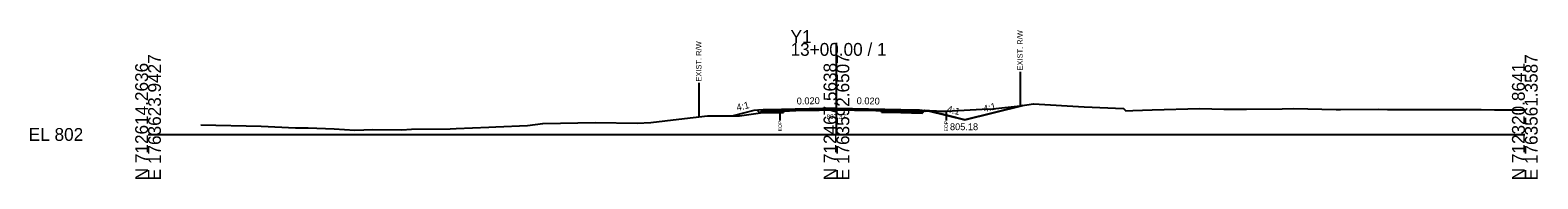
# Model space of a CAD drawing. Extents: x -26 to 1303, y -10 to 9524.
# Drawn here: x -25.7 to 302.8, y 2990.3 to 3022.8 of the extents above; entities that cross this region are included whole.
import ezdxf

# ---------------------------------------------------------------- set-up
doc = ezdxf.new("R2010")
doc.units = 0
for name, color, linetype in [('Default', 7, 'Continuous'), ('Exist CMT Pavement', 7, 'Continuous'), ('Exist Cross Section Cell', 7, 'Continuous'), ('Exist XS Center Line Elevation Label', 7, 'Continuous'), ('Exist XS Ground Line', 7, 'Continuous'), ('Old_Level_10', 7, 'Continuous'), ('Prop CMT Pvmt Course 1', 7, 'Continuous'), ('Prop CMT Pvmt Course 3', 7, 'Continuous'), ('Prop CMT Pvmt Surface', 7, 'Continuous'), ('Prop CMT Pvmt Surface Shoulder', 7, 'Continuous'), ('Prop CMT Shld Paved Course 1', 7, 'Continuous'), ('Prop CMT Shld Paved Course 3', 7, 'Continuous'), ('Prop CMT Slope Grass', 7, 'Continuous'), ('Prop CMT Subgrade Earthwork', 7, 'Continuous'), ('Prop XS Ditch Standard Text', 7, 'Continuous'), ('Prop XS Earthwork Shape', 7, 'Continuous'), ('Prop XS SE Text', 7, 'Continuous'), ('Prop XS Side Slope Text', 7, 'Continuous')]:
    doc.layers.add(name, color=color, linetype=linetype)

msp = doc.modelspace()

# ---------------------------------------------------------------- linework, layer by layer
at = {"layer": 'Exist CMT Pavement'}
msp.add_lwpolyline([(138.43, 3005.15), (138.43, 3005.15), (139.08, 3005.17), (139.77, 3005.18), (140.31, 3005.19), (141.12, 3005.21), (143.67, 3005.27), (144.73, 3005.28), (146.23, 3005.29), (148.07, 3005.34), (148.4, 3005.35), (148.78, 3005.36), (149.39, 3005.38), (150, 3005.37), (151.34, 3005.34), (152.29, 3005.34), (153.9, 3005.31), (154.39, 3005.3), (156.71, 3005.27), (158.61, 3005.25), (158.98, 3005.25), (159.79, 3005.25)], dxfattribs=at)
at = {"layer": 'Exist Cross Section Cell'}
for p, q in [((150, 3000), (150, 3019.95)), ((0, 3000), (150, 3000)), ((150, 3000), (300, 3000))]:
    msp.add_line(p, q, dxfattribs=at)
at = {"layer": 'Exist XS Ground Line'}
msp.add_lwpolyline([(11.47, 3002.11), (24.64, 3001.78), (32.11, 3001.46), (34.86, 3001.42), (40.54, 3001.19), (45.09, 3000.92), (48.97, 3001.08), (55.32, 3001.04), (57.4, 3001.12), (65.83, 3001.22), (67.16, 3001.28), (74.26, 3001.58), (75.77, 3001.65), (82.68, 3001.98), (86, 3002.4), (97.52, 3002.6), (106.59, 3002.43), (109.57, 3002.61), (115.63, 3003.3), (121.92, 3004.06), (126.21, 3004.09), (128.87, 3004.09), (134.44, 3004.83), (137.7, 3005.12), (138.03, 3005.13), (138.43, 3005.15), (139.08, 3005.17), (139.77, 3005.18), (140.31, 3005.19), (141.12, 3005.21), (143.67, 3005.27), (144.73, 3005.28), (146.23, 3005.29), (148.07, 3005.34), (148.4, 3005.35), (148.78, 3005.36), (149.39, 3005.38), (150, 3005.37), (151.34, 3005.34), (152.29, 3005.34), (153.9, 3005.31), (154.39, 3005.3), (156.71, 3005.27), (158.61, 3005.25), (158.98, 3005.25), (159.79, 3005.25), (160.92, 3005.23), (161.57, 3005.21), (162.88, 3005.19), (164.12, 3005.17), (166.13, 3005.15), (166.68, 3005.15), (168.7, 3005.12), (169.38, 3005.11), (171.79, 3005.12), (172.65, 3005.1), (173.23, 3005.08), (173.91, 3005.08), (181.76, 3005.48), (184.1, 3005.56), (190.05, 3006.25), (192.97, 3006.65), (204, 3006.04), (212.56, 3005.68), (213.06, 3005.18), (214.56, 3005.25), (218.82, 3005.37), (229.16, 3005.68), (234.4, 3005.51), (239.39, 3005.53), (247.09, 3005.55), (249.62, 3005.63), (258.92, 3005.43), (259.84, 3005.41), (268.11, 3005.48), (270.07, 3005.47), (276.54, 3005.46), (280.3, 3005.46), (284.97, 3005.45), (290.52, 3005.41), (293.4, 3005.4), (300, 3005.37)], dxfattribs=at)
at = {"layer": 'Old_Level_10'}
for p, q in [((190, 3013.65), (190, 3006.25)), ((120, 3011.23), (120, 3003.83)), ((137.7, 3005.12), (137.7, 3003.07)), ((173.91, 3005.08), (173.91, 3003.03))]:
    msp.add_line(p, q, dxfattribs=at)
at = {"layer": 'Prop CMT Pvmt Course 1'}
for points in [[(150, 3005.7), (138, 3005.46)], [(138, 3005.46), (138, 3005.21)], [(138, 3005.21), (138.43, 3005.22)], [(138.43, 3005.22), (150, 3005.45)], [(138.43, 3005.22), (138.43, 3005.22)], [(150, 3005.45), (150, 3005.7)], [(150, 3005.7), (164, 3005.42)], [(150, 3005.45), (150, 3005.45), (150, 3005.45)], [(159.79, 3005.26), (150, 3005.45)], [(164, 3005.17), (159.79, 3005.26)], [(159.79, 3005.26), (159.79, 3005.26)], [(164, 3005.42), (164, 3005.17)]]:
    msp.add_lwpolyline(points, dxfattribs=at)
at = {"layer": 'Prop CMT Pvmt Course 3'}
for points in [[(138.43, 3005.22), (138, 3005.21)], [(138, 3005.21), (138, 3004.79)], [(138, 3004.79), (138.43, 3004.8)], [(138.43, 3004.8), (138.43, 3005.22)], [(159.79, 3005.26), (164, 3005.17)], [(159.79, 3004.84), (159.79, 3005.26)], [(164, 3004.75), (159.79, 3004.84)], [(164, 3005.17), (164, 3004.75)]]:
    msp.add_lwpolyline(points, dxfattribs=at)
at = {"layer": 'Prop CMT Pvmt Surface'}
for points in [[(150, 3005.7), (138, 3005.46)], [(150, 3005.7), (164, 3005.42)]]:
    msp.add_lwpolyline(points, dxfattribs=at)
at = {"layer": 'Prop CMT Pvmt Surface Shoulder'}
for points in [[(138, 3005.46), (134, 3005.38)], [(164, 3005.42), (168, 3005.34)]]:
    msp.add_lwpolyline(points, dxfattribs=at)
at = {"layer": 'Prop CMT Shld Paved Course 1'}
for points in [[(138, 3005.46), (134, 3005.38), (133.74, 3005.13)], [(133.74, 3005.13), (138, 3005.21)], [(138, 3005.21), (138, 3005.46)], [(164, 3005.42), (168, 3005.34), (168.26, 3005.09)], [(164, 3005.17), (164, 3005.42)], [(168.26, 3005.09), (164, 3005.17)]]:
    msp.add_lwpolyline(points, dxfattribs=at)
at = {"layer": 'Prop CMT Shld Paved Course 3'}
for points in [[(133.74, 3005.13), (133.32, 3004.7)], [(133.32, 3004.7), (138, 3004.79)], [(138, 3005.21), (133.74, 3005.13)], [(138, 3004.88), (138, 3005.21)], [(164, 3005.17), (168.26, 3005.09)], [(164, 3004.84), (164, 3005.17)], [(168.68, 3004.66), (164, 3004.75)], [(168.26, 3005.09), (168.68, 3004.66)]]:
    msp.add_lwpolyline(points, dxfattribs=at)
at = {"layer": 'Prop CMT Slope Grass'}
for points in [[(168, 3005.34), (170, 3005.18), (178, 3003.18), (190.59, 3006.33)], [(134, 3005.38), (132, 3005.22), (127.48, 3004.09)]]:
    msp.add_lwpolyline(points, dxfattribs=at)
at = {"layer": 'Prop CMT Subgrade Earthwork'}
for p, q in [((138, 3004.79), (133.32, 3004.7)), ((138.43, 3004.8), (138, 3004.79)), ((138.43, 3004.8), (138.43, 3005.15)), ((159.79, 3004.84), (159.79, 3005.25)), ((159.79, 3004.84), (164, 3004.75)), ((164, 3004.75), (168.68, 3004.66))]:
    msp.add_line(p, q, dxfattribs=at)
for points in [[(132.74, 3005.28), (133.32, 3004.7)], [(169.26, 3005.24), (168.68, 3004.66)]]:
    msp.add_lwpolyline(points, dxfattribs=at)
at = {"layer": 'Prop XS Earthwork Shape'}
for points in [[(181.76, 3005.48), (184.1, 3005.56), (190.05, 3006.25), (190.59, 3006.33), (178, 3003.18), (170.26, 3005.12), (171.79, 3005.12), (172.65, 3005.1), (173.23, 3005.08), (173.91, 3005.08)], [(132, 3005.22), (127.48, 3004.09), (128.87, 3004.09), (133.47, 3004.7), (133.32, 3004.7), (132.74, 3005.28)], [(138.43, 3004.8), (138, 3004.79), (133.47, 3004.7), (134.44, 3004.83), (137.7, 3005.12), (138.03, 3005.13), (138.43, 3005.15)], [(159.79, 3004.84), (159.79, 3005.25), (160.92, 3005.23), (161.57, 3005.21), (162.88, 3005.19), (164.12, 3005.17), (166.13, 3005.15), (166.68, 3005.15), (168.7, 3005.12), (169.14, 3005.12), (168.68, 3004.66), (164, 3004.75)], [(169.14, 3005.12), (169.38, 3005.11), (170.26, 3005.12), (170, 3005.18), (169.26, 3005.24)]]:
    msp.add_lwpolyline(points, close=True, dxfattribs=at)

# ---------------------------------------------------------------- texts
at = {"layer": 'Default'}
msp.add_text('-', height=0.0001, dxfattribs=at).set_placement((0, 3000))
at = {"layer": 'Exist Cross Section Cell'}
for s, p in [('Y1', (140, 3019.95)), ('13+00.00 / 1', (140, 3017.15)), ('EL 802', (-26, 2998.6))]:
    msp.add_text(s, height=2.8, dxfattribs=at).set_placement(p)
for s, p in [('E 1763623.9427', (2.8, 2990)), ('E 1763592.6507', (152.8, 2990)), ('E 1763561.3587', (302.8, 2990)), ('N 712614.2636', (0, 2990)), ('N 712467.5638', (150, 2990)), ('N 712320.8641', (300, 2990))]:
    msp.add_text(s, height=2.8, rotation=90, dxfattribs=at).set_placement(p)
at = {"layer": 'Exist XS Center Line Elevation Label'}
msp.add_text('807.37', height=1, dxfattribs=at).set_placement((147.85, 3003.37))
at = {"layer": 'Old_Level_10'}
for s, height, p in [('EXIST. R/W', 1.181, (120.59, 3011.53)), ('EXIST. R/W', 1.181, (190.59, 3013.95)), ('EOP', 0.787, (138.1, 3000.67)), ('EOP', 0.787, (174.3, 3000.64))]:
    msp.add_text(s, height=height, rotation=90, dxfattribs=at).set_placement(p)
at = {"layer": 'Prop XS Ditch Standard Text'}
msp.add_text('805.18', height=1.5, dxfattribs=at).set_placement((174.74, 3000.93))
at = {"layer": 'Prop XS SE Text'}
for rotation, p in [(1.1458, (141.36, 3006.53)), (358.8542, (154.4, 3006.61))]:
    msp.add_text('0.020', height=1.5, rotation=rotation, dxfattribs=at).set_placement(p)
at = {"layer": 'Prop XS Side Slope Text'}
for rotation, p in [(14.0362, (128.41, 3005.1)), (345.9638, (173.98, 3004.88)), (14.0363, (182.2, 3004.82))]:
    msp.add_text('4:1', height=1.5, rotation=rotation, dxfattribs=at).set_placement(p)

doc.saveas('drawing.dxf')
